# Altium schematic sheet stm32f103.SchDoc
size A3
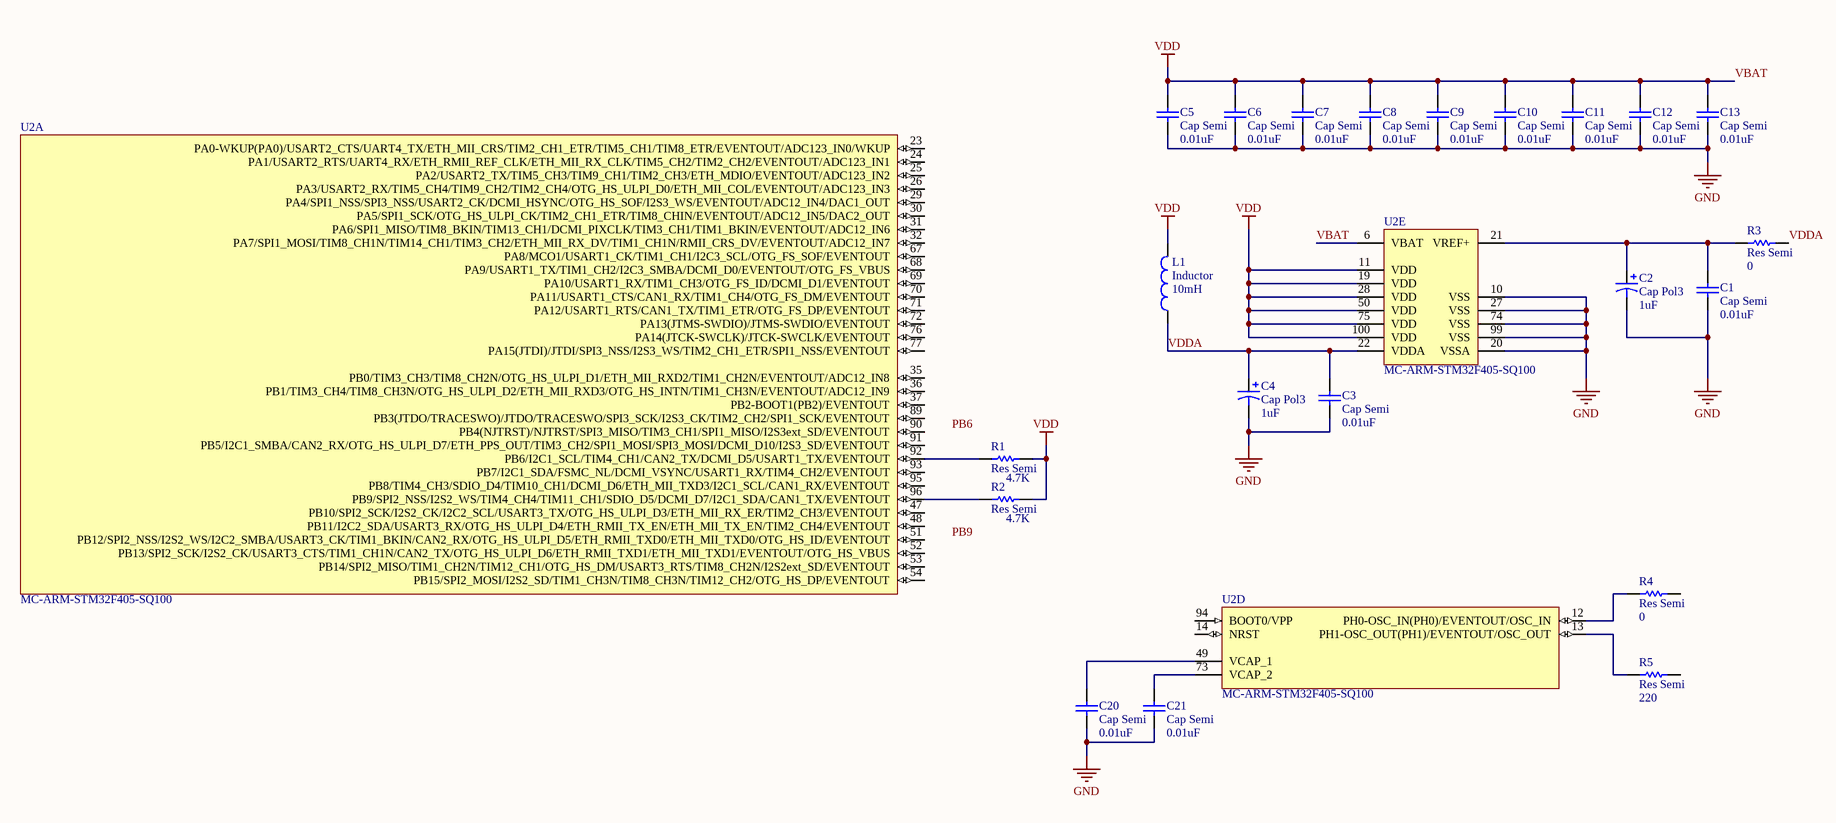
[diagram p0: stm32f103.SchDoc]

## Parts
C1  Cap Semi  value 0.01uF  [CAPC1608L]
C2  Cap Pol3  value 1uF  [CAPC2012L]
C3  Cap Semi  value 0.01uF  [CAPC1608L]
C4  Cap Pol3  value 1uF  [CAPC2012L]
C5  Cap Semi  value 0.01uF  [CAPC1608L]
C6  Cap Semi  value 0.01uF  [CAPC1608L]
C7  Cap Semi  value 0.01uF  [CAPC1608L]
C8  Cap Semi  value 0.01uF  [CAPC1608L]
C9  Cap Semi  value 0.01uF  [CAPC1608L]
C10  Cap Semi  value 0.01uF  [CAPC1608L]
C11  Cap Semi  value 0.01uF  [CAPC1608L]
C12  Cap Semi  value 0.01uF  [CAPC1608L]
C13  Cap Semi  value 0.01uF  [CAPC1608L]
C20  Cap Semi  value 0.01uF  [CAPC1608L]
C21  Cap Semi  value 0.01uF  [CAPC1608L]
L1  Inductor  value 10mH  [INDC1608L]
R1  Res Semi  value 4.7K  [RESC1608L]
R2  Res Semi  value 4.7K  [RESC1608L]
R3  Res Semi  value 0  [RESC1608L]
R4  Res Semi  value 0  [RESC1608L]
R5  Res Semi  value 220  [RESC1608L]
U2  MC-ARM-STM32F405-SQ100  (parts A,D,E of 5)

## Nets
GND: C1.1 C2.2 C3.1 C4.2 C5.1 C6.1 C7.1 C8.1 C9.1 C10.1 C11.1 C12.1 C13.1 C20.1 C21.1 U2.10(VSS) U2.20(VSSA) U2.27(VSS) U2.74(VSS) U2.99(VSS)
VBAT: C5.2 C6.2 C7.2 C8.2 C9.2 C10.2 C11.2 C12.2 C13.2 L1.2 R1.2 R2.2 U2.6(VBAT) U2.11(VDD) U2.19(VDD) U2.28(VDD) U2.50(VDD) U2.75(VDD) U2.100(VDD)  [also labelled VDD]
VDDA: C3.2 C4.1 L1.1 R3.2 U2.22(VDDA)
NetC1_2: C1.2 C2.1 R3.1 U2.21(VREF+)
NetC20_2: C20.2 U2.49(VCAP_1)
NetC21_2: C21.2 U2.73(VCAP_2)
NetR1_1: R1.1 U2.92(PB6/I2C1_SCL/TIM4_CH1/CAN2_TX/DCMI_D5/USART1_TX/EVENTOUT)
NetR2_1: R2.1 U2.96(PB9/SPI2_NSS/I2S2_WS/TIM4_CH4/TIM11_CH1/SDIO_D5/DCMI_D7/I2C1_SDA/CAN1_TX/EVENTOUT)
NetR4_1: R4.1 U2.12(PH0-OSC_IN(PH0)/EVENTOUT/OSC_IN)
NetR5_1: R5.1 U2.13(PH1-OSC_OUT(PH1)/EVENTOUT/OSC_OUT)

Not connected (* = marked no-connect by the designer): R4 2; R5 2; U2 14(NRST) 23(PA0-WKUP(PA0)/USART2_CTS/UART4_TX/ETH_MII_CRS/TIM2_CH1_ETR/TIM5_CH1/TIM8_ETR/EVENTOUT/ADC123_IN0/WKUP) 24(PA1/USART2_RTS/UART4_RX/ETH_RMII_REF_CLK/ETH_MII_RX_CLK/TIM5_CH2/TIM2_CH2/EVENTOUT/ADC123_IN1) 25(PA2/USART2_TX/TIM5_CH3/TIM9_CH1/TIM2_CH3/ETH_MDIO/EVENTOUT/ADC123_IN2) 26(PA3/USART2_RX/TIM5_CH4/TIM9_CH2/TIM2_CH4/OTG_HS_ULPI_D0/ETH_MII_COL/EVENTOUT/ADC123_IN3) 29(PA4/SPI1_NSS/SPI3_NSS/USART2_CK/DCMI_HSYNC/OTG_HS_SOF/I2S3_WS/EVENTOUT/ADC12_IN4/DAC1_OUT) 30(PA5/SPI1_SCK/OTG_HS_ULPI_CK/TIM2_CH1_ETR/TIM8_CHIN/EVENTOUT/ADC12_IN5/DAC2_OUT) 31(PA6/SPI1_MISO/TIM8_BKIN/TIM13_CH1/DCMI_PIXCLK/TIM3_CH1/TIM1_BKIN/EVENTOUT/ADC12_IN6) 32(PA7/SPI1_MOSI/TIM8_CH1N/TIM14_CH1/TIM3_CH2/ETH_MII_RX_DV/TIM1_CH1N/RMII_CRS_DV/EVENTOUT/ADC12_IN7) 35(PB0/TIM3_CH3/TIM8_CH2N/OTG_HS_ULPI_D1/ETH_MII_RXD2/TIM1_CH2N/EVENTOUT/ADC12_IN8) 36(PB1/TIM3_CH4/TIM8_CH3N/OTG_HS_ULPI_D2/ETH_MII_RXD3/OTG_HS_INTN/TIM1_CH3N/EVENTOUT/ADC12_IN9) 37(PB2-BOOT1(PB2)/EVENTOUT) 47(PB10/SPI2_SCK/I2S2_CK/I2C2_SCL/USART3_TX/OTG_HS_ULPI_D3/ETH_MII_RX_ER/TIM2_CH3/EVENTOUT) 48(PB11/I2C2_SDA/USART3_RX/OTG_HS_ULPI_D4/ETH_RMII_TX_EN/ETH_MII_TX_EN/TIM2_CH4/EVENTOUT) 51(PB12/SPI2_NSS/I2S2_WS/I2C2_SMBA/USART3_CK/TIM1_BKIN/CAN2_RX/OTG_HS_ULPI_D5/ETH_RMII_TXD0/ETH_MII_TXD0/OTG_HS_ID/EVENTOUT) 52(PB13/SPI2_SCK/I2S2_CK/USART3_CTS/TIM1_CH1N/CAN2_TX/OTG_HS_ULPI_D6/ETH_RMII_TXD1/ETH_MII_TXD1/EVENTOUT/OTG_HS_VBUS) 53(PB14/SPI2_MISO/TIM1_CH2N/TIM12_CH1/OTG_HS_DM/USART3_RTS/TIM8_CH2N/I2S2ext_SD/EVENTOUT) 54(PB15/SPI2_MOSI/I2S2_SD/TIM1_CH3N/TIM8_CH3N/TIM12_CH2/OTG_HS_DP/EVENTOUT) 67(PA8/MCO1/USART1_CK/TIM1_CH1/I2C3_SCL/OTG_FS_SOF/EVENTOUT) 68(PA9/USART1_TX/TIM1_CH2/I2C3_SMBA/DCMI_D0/EVENTOUT/OTG_FS_VBUS) 69(PA10/USART1_RX/TIM1_CH3/OTG_FS_ID/DCMI_D1/EVENTOUT) 70(PA11/USART1_CTS/CAN1_RX/TIM1_CH4/OTG_FS_DM/EVENTOUT) 71(PA12/USART1_RTS/CAN1_TX/TIM1_ETR/OTG_FS_DP/EVENTOUT) 72(PA13(JTMS-SWDIO)/JTMS-SWDIO/EVENTOUT) 76(PA14(JTCK-SWCLK)/JTCK-SWCLK/EVENTOUT) 77(PA15(JTDI)/JTDI/SPI3_NSS/I2S3_WS/TIM2_CH1_ETR/SPI1_NSS/EVENTOUT) 89(PB3(JTDO/TRACESWO)/JTDO/TRACESWO/SPI3_SCK/I2S3_CK/TIM2_CH2/SPI1_SCK/EVENTOUT) 90(PB4(NJTRST)/NJTRST/SPI3_MISO/TIM3_CH1/SPI1_MISO/I2S3ext_SD/EVENTOUT) 91(PB5/I2C1_SMBA/CAN2_RX/OTG_HS_ULPI_D7/ETH_PPS_OUT/TIM3_CH2/SPI1_MOSI/SPI3_MOSI/DCMI_D10/I2S3_SD/EVENTOUT) 93(PB7/I2C1_SDA/FSMC_NL/DCMI_VSYNC/USART1_RX/TIM4_CH2/EVENTOUT) 94(BOOT0/VPP) 95(PB8/TIM4_CH3/SDIO_D4/TIM10_CH1/DCMI_D6/ETH_MII_TXD3/I2C1_SCL/CAN1_RX/EVENTOUT)

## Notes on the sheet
- Labels drawn without touching a wire or pin: PB6, PB9

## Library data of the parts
C1 C3 C5-C13 C20 C21 = Cap Semi: Capacitor (Semiconductor SIM Model)
C2 C4 = Cap Pol3: Polarized Capacitor (Surface Mount)
L1 = Inductor: Code_IEC: 1005
R1-R5 = Res Semi: Semiconductor Resistor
